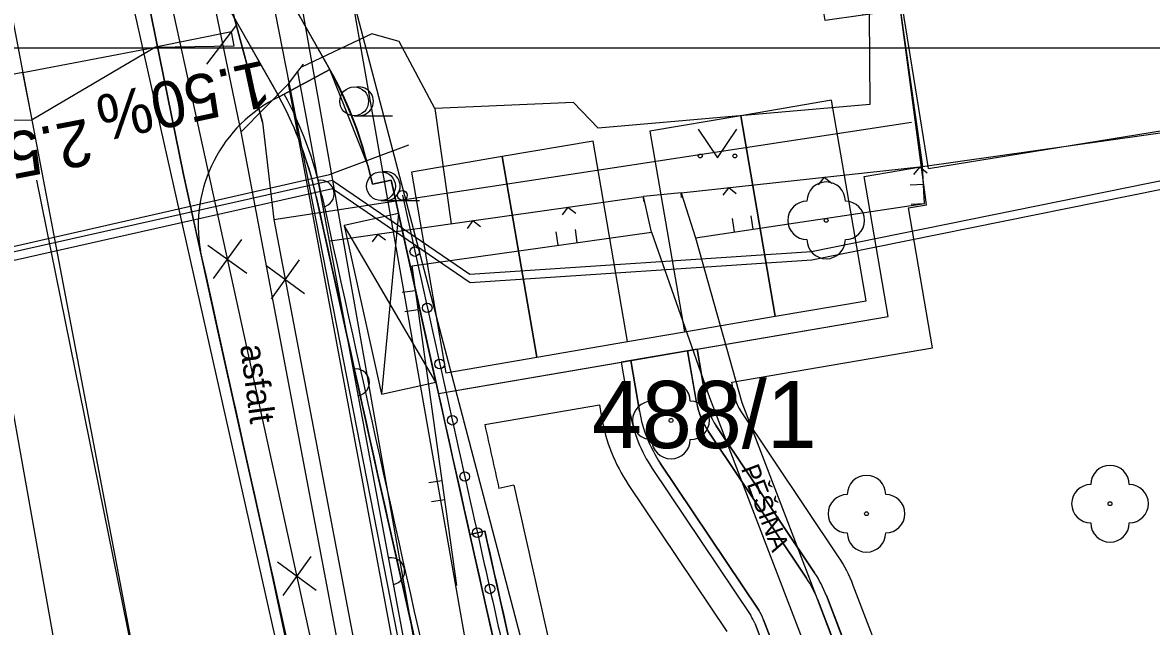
# Model space of a CAD drawing. Extents: x -643342 to -638635, y -1201752 to -1189948.
# Drawn here: x -639502.04 to -639472.65, y -1192680.44 to -1192664.71 of the extents above; entities that cross this region are included whole.
import ezdxf

# ---------------------------------------------------------------- set-up
doc = ezdxf.new("R2010")
doc.units = 0
for name, color, linetype in [('-zbytky_kruháče', 7, 'Continuous'), ('41', 7, 'Continuous'), ('5', 7, 'Continuous'), ('IS_EL_NN_NADZEMNÍ', 7, 'Continuous'), ('IS_TELEF_MISTNI_ZAMERENO', 7, 'Continuous'), ('IS_VODOVOD_PRIPOJKA DOMOVNÍ', 7, 'Continuous'), ('K-HRANICE_KN', 7, 'Continuous'), ('K-ČÍSLA_PARCEL', 7, 'Continuous'), ('kanalizace_dešťová_stávající', 7, 'Continuous'), ('N-CHODNIK', 7, 'Continuous'), ('N-CHODNIK-PŘÍMĚTICE', 7, 'Continuous'), ('N-KAN_DEST_TRASA-NÁVRH', 7, 'Continuous'), ('N-OBVOD STAVBY 06', 7, 'Continuous'), ('N-oploceni', 7, 'Continuous'), ('N-OSA', 7, 'Continuous'), ('N-PLOT', 7, 'Continuous'), ('N-rusene_vedeni', 7, 'Continuous'), ('N-SILNICE', 7, 'Continuous'), ('N-SO101_KLOPENI', 7, 'Continuous'), ('N-SRAFY_PLOCHY', 7, 'Continuous'), ('N-ZDI', 7, 'Continuous'), ('N-úprava plochu u obecního úřadu', 7, 'Continuous'), ('Vrstva 13', 7, 'Continuous'), ('Z-budovy', 7, 'Continuous'), ('Z-hrany_a_čáry', 7, 'Continuous'), ('Z-popisy', 7, 'Continuous'), ('Z-stromy', 7, 'Continuous'), ('Z-značky', 7, 'Continuous')]:
    doc.layers.add(name, color=color, linetype=linetype)

# ---------------------------------------------------------------- blocks, each defined once
blk = doc.blocks.new('RAMA24')
at = {"layer": 'Vrstva 13'}
for p in [(-29700, 0), (-21000, 0)]:
    blk.add_line(p, (0, 0), dxfattribs=at)

msp = doc.modelspace()

# ---------------------------------------------------------------- linework, layer by layer
at = {"layer": '-zbytky_kruháče'}
msp.add_line((-639501.68, -1192668.815), (-639498.7, -1192683.504), dxfattribs=at)
at = {"layer": '5'}
for p, q in [((-639478.686, -1192668.468), (-639478.843, -1192668.663)), ((-639478.686, -1192668.468), (-639478.491, -1192668.625)), ((-639478.586, -1192668.927), (-639478.935, -1192668.945)), ((-639478.56, -1192669.426), (-639478.909, -1192669.444))]:
    msp.add_line(p, q, dxfattribs=at)
at = {"layer": 'IS_EL_NN_NADZEMNÍ'}
for p, q in [((-639488.19, -1192693.98), (-639494.86, -1192656.13)), ((-639489.5, -1192694.06), (-639496.16, -1192656.39))]:
    msp.add_line(p, q, dxfattribs=at)
msp.add_lwpolyline([(-639495.51, -1192656.21), (-639485.819, -1192693.156)], dxfattribs=at)
at = {"layer": 'IS_TELEF_MISTNI_ZAMERENO'}
for p, q in [((-639498.66, -1192656.66), (-639495.8, -1192667.3)), ((-639495.8, -1192667.3), (-639498.66, -1192656.66)), ((-639495.8, -1192667.3), (-639495.5, -1192669.84)), ((-639495.5, -1192669.84), (-639478.9, -1192667.3)), ((-639495.5, -1192669.84), (-639490.34, -1192697.09))]:
    msp.add_line(p, q, dxfattribs=at)
at = {"layer": 'IS_VODOVOD_PRIPOJKA DOMOVNÍ'}
for points in [[(-639508.251, -1192671.127), (-639508.092, -1192671.093), (-639507.998, -1192671.075), (-639507.374, -1192671.693), (-639494.05, -1192668.667), (-639491.986, -1192667.889)], [(-639508.152, -1192671.995), (-639507.95, -1192671.95), (-639493.98, -1192668.81), (-639490.4, -1192671.26), (-639481.5, -1192670.67), (-639471.54, -1192668.65), (-639471.232, -1192668.584)], [(-639508.128, -1192672.212), (-639507.94, -1192672.17), (-639493.97, -1192669.03), (-639490.39, -1192671.48), (-639481.49, -1192670.89), (-639471.53, -1192668.87), (-639471.212, -1192668.802)]]:
    msp.add_lwpolyline(points, dxfattribs=at)
at = {"layer": 'K-HRANICE_KN'}
for p, q in [((-639490.92, -1192687.58), (-639497.61, -1192653.45)), ((-639478.46, -1192668.51), (-639479.13, -1192664.31)), ((-639478.46, -1192668.51), (-639470.96, -1192667.29))]:
    msp.add_line(p, q, dxfattribs=at)
at = {"layer": 'kanalizace_dešťová_stávající'}
msp.add_lwpolyline([(-639501.4, -1192649.45), (-639493.45, -1192685.76), (-639489, -1192707.04), (-639487.73, -1192718.33)], dxfattribs=at)
at = {"layer": 'N-CHODNIK'}
for p, q in [((-639492.252, -1192669.679), (-639492.695, -1192674.386)), ((-639491.279, -1192674.072), (-639493.668, -1192669.992))]:
    msp.add_line(p, q, dxfattribs=at)
msp.add_lwpolyline([(-639492.252, -1192669.679), (-639493.668, -1192669.992), (-639492.695, -1192674.386), (-639491.279, -1192674.072)], close=True, dxfattribs=at)
at = {"layer": 'N-CHODNIK-PŘÍMĚTICE'}
for p, q in [((-639494.154, -1192665.729), (-639497.026, -1192660.652)), ((-639495.46, -1192666.467), (-639498.331, -1192661.391)), ((-639495.363, -1192666.642), (-639494.043, -1192665.93)), ((-639492.932, -1192668.919), (-639492.444, -1192668.812))]:
    msp.add_line(p, q, dxfattribs=at)
for centre, radius, start, end in [((-639504.164, -1192671.391), 11.5, 12.4113, 29.4957), ((-639504.164, -1192671.391), 10, 12.4113, 29.4957), ((-639504.164, -1192671.391), 10.15, 12.4113, 28.3512), ((-636647.689, -1192042.763), 2912.828, 192.411302, 192.702157), ((-636647.689, -1192042.763), 2914.828, 192.411302, 192.702157), ((-636647.688, -1192042.763), 2914.679, 192.411302, 192.702157)]:
    msp.add_arc(centre, radius, start, end, dxfattribs=at)
at = {"layer": 'N-KAN_DEST_TRASA-NÁVRH'}
msp.add_lwpolyline([(-639583.962, -1192528.01), (-639550.452, -1192564.184), (-639529.583, -1192588.026), (-639514.491, -1192612.048), (-639507.737, -1192644.326), (-639498.832, -1192694.254), (-639511.439, -1192713.331), (-639516.613, -1192716.507), (-639553.938, -1192703.739), (-639570.485, -1192701.616), (-639578.687, -1192703.18)], dxfattribs=at)
at = {"layer": 'N-OBVOD STAVBY 06'}
for points in [[(-639483.574, -1192674.073), (-639478.35, -1192673.177), (-639478.975, -1192669.537), (-639478.509, -1192669.457), (-639479.189, -1192664.375), (-639480.16, -1192664.511), (-639480.679, -1192661.378), (-639479.62, -1192661.17), (-639480.18, -1192657.1), (-639473.476, -1192655.963), (-639474.659, -1192649.068), (-639480.958, -1192650.354), (-639492.683, -1192652.747), (-639494.955, -1192656.085)], [(-639483.514, -1192674.42), (-639483.574, -1192674.073)], [(-639490.011, -1192675.178), (-639487.024, -1192674.665)], [(-639487.024, -1192674.665), (-639486.967, -1192674.995)], [(-639480.798, -1192678.624), (-639483.363, -1192674.79)], [(-639489.25, -1192676.757), (-639489.64, -1192676.844)], [(-639486.272, -1192676.736), (-639483.707, -1192680.57)], [(-639474.551, -1192702.67), (-639474.362, -1192695.153), (-639480.414, -1192679.366)]]:
    msp.add_lwpolyline(points, dxfattribs=at)
for centre, radius, start, end in [((-639482.532, -1192674.234), 1, 190.7418, 213.7845), ((-636647.689, -1192042.763), 2911.828, 192.543933, 192.577514), ((-639482.532, -1192674.234), 4.5, 189.7364, 213.7845), ((-635637.009, -1191816.112), 3947.21, 192.593871, 192.685804), ((-639483.916, -1192680.709), 3.751, 20.9887, 33.7821)]:
    msp.add_arc(centre, radius, start, end, dxfattribs=at)
at = {"layer": 'N-oploceni'}
for centre in [(-639492.156, -1192669.207), (-639491.832, -1192670.672), (-639491.508, -1192672.137), (-639491.182, -1192673.601), (-639490.856, -1192675.065), (-639490.53, -1192676.53), (-639490.203, -1192677.994), (-639489.875, -1192679.457)]:
    msp.add_circle(centre, 0.125, dxfattribs=at)
for centre, radius, start, end in [((-636647.689, -1192042.763), 2912.628, 192.42012, 192.597178), ((-636648.374, -1192042.917), 2911.926, 192.597169, 192.702169)]:
    msp.add_arc(centre, radius, start, end, dxfattribs=at)
at = {"layer": 'N-OSA'}
msp.add_lwpolyline([(-639498.81, -1192682.926), (-639506.825, -1192640.839)], dxfattribs=at)
at = {"layer": 'N-PLOT'}
for points in [[(-639484.729, -1192673.257), (-639479.505, -1192672.361), (-639480.13, -1192668.721), (-639478.61, -1192668.46)], [(-639491.018, -1192674.336), (-639486.207, -1192673.511)]]:
    msp.add_lwpolyline(points, dxfattribs=at)
at = {"layer": 'N-rusene_vedeni'}
for p, q in [((-639496.345, -1192670.361), (-639497.077, -1192671.374)), ((-639497.217, -1192670.502), (-639496.204, -1192671.233)), ((-639495.712, -1192671.029), (-639494.699, -1192671.761)), ((-639494.84, -1192670.889), (-639495.571, -1192671.902)), ((-639494.538, -1192678.614), (-639495.27, -1192679.627)), ((-639495.41, -1192678.755), (-639494.397, -1192679.487))]:
    msp.add_line(p, q, dxfattribs=at)
at = {"layer": 'N-SILNICE'}
msp.add_line((-639497.852, -1192668.663), (-639500.522, -1192655.528), dxfattribs=at)
for centre, radius, start, end in [((-639493.725, -1192670.01), 3.745, 115.9414, 189.8695), ((-636647.693, -1192042.764), 2918.074, 192.385621, 192.66671)]:
    msp.add_arc(centre, radius, start, end, dxfattribs=at)
at = {"layer": 'N-SO101_KLOPENI'}
for points in [[(-639496.606, -1192664.951), (-639498.578, -1192665.348), (-639496.538, -1192665.316), (-639496.606, -1192664.951)], [(-639502.032, -1192666.011), (-639498.578, -1192665.348), (-639501.797, -1192667.239), (-639502.032, -1192666.011)], [(-639502.032, -1192666.011), (-639498.578, -1192665.348), (-639501.797, -1192667.239), (-639502.032, -1192666.011)], [(-639502.032, -1192666.011), (-639508.542, -1192667.256), (-639501.797, -1192667.239), (-639502.032, -1192666.011)]]:
    msp.add_lwpolyline(points, close=True, dxfattribs=at)
at = {"layer": 'N-SRAFY_PLOCHY'}
for p, q in [((-639500.535, -1192655.464), (-639497.852, -1192668.663)), ((-639494.043, -1192665.93), (-639497.026, -1192660.652)), ((-639495.363, -1192666.642), (-639498.331, -1192661.391)), ((-639498.331, -1192661.391), (-639495.363, -1192666.642)), ((-639496.428, -1192661.709), (-639494.666, -1192664.824)), ((-639498.437, -1192665.785), (-639498.993, -1192663.053)), ((-639478.61, -1192668.46), (-639479.189, -1192664.375)), ((-639494.666, -1192664.824), (-639494.043, -1192665.93)), ((-639497.852, -1192668.663), (-639498.437, -1192665.785)), ((-639494.043, -1192665.93), (-639495.363, -1192666.642)), ((-639495.363, -1192666.642), (-639494.043, -1192665.93)), ((-639493.053, -1192668.423), (-639492.932, -1192668.919)), ((-639497.463, -1192670.433), (-639497.852, -1192668.663)), ((-639497.852, -1192668.663), (-639497.415, -1192670.652)), ((-639480.13, -1192668.721), (-639478.61, -1192668.46)), ((-639492.932, -1192668.919), (-639492.444, -1192668.812)), ((-639492.444, -1192668.812), (-639492.932, -1192668.919)), ((-639492.444, -1192668.812), (-639491.212, -1192674.369)), ((-639490.398, -1192678.037), (-639492.444, -1192668.812)), ((-639479.505, -1192672.361), (-639480.13, -1192668.721)), ((-639494.397, -1192669.241), (-639493.598, -1192672.853)), ((-639492.798, -1192676.465), (-639494.397, -1192669.241)), ((-639496.938, -1192672.813), (-639497.463, -1192670.433)), ((-639497.415, -1192670.652), (-639496.308, -1192675.652)), ((-639485.098, -1192673.32), (-639479.505, -1192672.361)), ((-639496.409, -1192675.197), (-639496.938, -1192672.813)), ((-639493.598, -1192672.853), (-639492.798, -1192676.465)), ((-639484.729, -1192673.257), (-639486.207, -1192673.511)), ((-639485.838, -1192673.447), (-639485.098, -1192673.32)), ((-639484.482, -1192673.215), (-639484.729, -1192673.257)), ((-639484.499, -1192674.597), (-639484.729, -1192673.257)), ((-639484.729, -1192673.257), (-639484.503, -1192674.572)), ((-639484.257, -1192674.53), (-639484.482, -1192673.215)), ((-639491.212, -1192674.369), (-639485.838, -1192673.447)), ((-639486.207, -1192673.511), (-639486.454, -1192673.553)), ((-639486.454, -1192673.553), (-639486.228, -1192674.868)), ((-639486.207, -1192673.511), (-639485.981, -1192674.826)), ((-639485.981, -1192674.826), (-639486.207, -1192673.511)), ((-639496.093, -1192676.622), (-639496.409, -1192675.197)), ((-639481.629, -1192679.18), (-639484.194, -1192675.346)), ((-639484.194, -1192675.346), (-639481.629, -1192679.18)), ((-639481.422, -1192679.041), (-639483.986, -1192675.207)), ((-639496.308, -1192675.652), (-639494.747, -1192682.638)), ((-639485.649, -1192676.319), (-639483.084, -1192680.153)), ((-639485.441, -1192676.18), (-639482.876, -1192680.014)), ((-639482.876, -1192680.014), (-639485.441, -1192676.18)), ((-639495.633, -1192678.683), (-639496.093, -1192676.622)), ((-639492.798, -1192676.465), (-639491.989, -1192680.075)), ((-639491.18, -1192683.684), (-639492.798, -1192676.465)), ((-639490.008, -1192677.95), (-639490.398, -1192678.037)), ((-639489.229, -1192683.245), (-639490.398, -1192678.037)), ((-639490.398, -1192678.037), (-639489.229, -1192683.245)), ((-639488.839, -1192683.157), (-639490.008, -1192677.95)), ((-639494.881, -1192682.21), (-639495.633, -1192678.683)), ((-639474.439, -1192697.747), (-639481.348, -1192679.724)), ((-639481.348, -1192679.724), (-639474.439, -1192697.747)), ((-639474.431, -1192697.068), (-639481.114, -1192679.634)), ((-639491.989, -1192680.075), (-639491.18, -1192683.684)), ((-639482.981, -1192680.351), (-639476.32, -1192697.73)), ((-639482.748, -1192680.261), (-639476.086, -1192697.64)), ((-639476.086, -1192697.64), (-639482.748, -1192680.261))]:
    msp.add_line(p, q, dxfattribs=at)
for centre, radius, start, end in [((-639502.453, -1192670.712), 9.675, 13.6827, 29.6226), ((-639504.164, -1192671.391), 11.5, 12.4113, 28.3512), ((-639493.725, -1192670.01), 3.745, 115.9414, 189.8695), ((-639493.725, -1192670.01), 3.745, 115.9414, 189.8695), ((-639504.164, -1192671.391), 10, 12.4113, 28.3512), ((-639504.164, -1192671.391), 10, 12.4113, 28.3512), ((-639482.532, -1192674.234), 2, 189.7364, 213.7845), ((-639482.532, -1192674.234), 2, 190.4493, 213.7845), ((-639482.532, -1192674.234), 1.75, 189.7364, 213.7853), ((-639482.532, -1192674.234), 3.75, 189.7364, 213.7845), ((-639482.532, -1192674.234), 3.5, 189.7364, 213.7845), ((-639482.532, -1192674.234), 3.5, 189.7364, 213.7845), ((-639483.915, -1192680.709), 2.75, 20.9911, 33.7845), ((-639483.915, -1192680.709), 2.75, 20.9911, 33.7845), ((-639483.915, -1192680.709), 3, 20.9911, 33.7845), ((-639483.915, -1192680.709), 1, 20.9911, 33.7845), ((-639483.915, -1192680.709), 1.25, 21.0132, 33.7845), ((-639483.915, -1192680.709), 1.25, 20.9911, 33.7845)]:
    msp.add_arc(centre, radius, start, end, dxfattribs=at)
at = {"layer": 'N-ZDI'}
msp.add_line((-639490.398, -1192678.037), (-639490.008, -1192677.95), dxfattribs=at)
msp.add_arc((-636647.689, -1192042.763), 2912.428, 192.597182, 192.702157, dxfattribs=at)
at = {"layer": 'N-úprava plochu u obecního úřadu'}
for p, q in [((-639493.053, -1192668.423), (-639494.043, -1192665.93)), ((-639486.292, -1192673.018), (-639484.813, -1192672.764)), ((-639485.838, -1192673.447), (-639485.098, -1192673.32)), ((-639484.729, -1192673.257), (-639484.503, -1192674.572)), ((-639484.482, -1192673.215), (-639484.257, -1192674.53)), ((-639486.454, -1192673.553), (-639486.228, -1192674.868)), ((-639486.207, -1192673.511), (-639485.981, -1192674.826)), ((-639484.194, -1192675.346), (-639481.629, -1192679.18)), ((-639483.986, -1192675.207), (-639481.422, -1192679.041)), ((-639485.649, -1192676.319), (-639483.084, -1192680.153)), ((-639485.441, -1192676.18), (-639482.876, -1192680.014))]:
    msp.add_line(p, q, dxfattribs=at)
for points in [[(-639493.053, -1192668.423), (-639492.932, -1192668.919), (-639492.444, -1192668.812), (-639491.212, -1192674.369), (-639485.838, -1192673.447), (-639485.098, -1192673.32), (-639479.505, -1192672.361), (-639480.13, -1192668.721), (-639478.61, -1192668.46), (-639479.189, -1192664.375), (-639481.15, -1192664.65), (-639481.66, -1192661.57), (-639479.62, -1192661.17), (-639480.18, -1192657.1), (-639474.463, -1192656.123), (-639475.639, -1192649.269), (-639480.958, -1192650.354), (-639491.279, -1192652.46), (-639494.129, -1192656.648)], [(-639497.026, -1192660.652), (-639496.428, -1192661.709), (-639494.666, -1192664.824), (-639494.043, -1192665.93)], [(-639480.979, -1192666.729), (-639483.344, -1192667.135), (-639482.448, -1192672.358), (-639480.082, -1192671.952), (-639480.979, -1192666.729)], [(-639483.344, -1192667.135), (-639485.71, -1192667.54), (-639484.813, -1192672.764), (-639482.448, -1192672.358), (-639483.344, -1192667.135)], [(-639487.188, -1192667.794), (-639489.553, -1192668.2), (-639488.657, -1192673.424), (-639486.292, -1192673.018), (-639487.188, -1192667.794)], [(-639489.553, -1192668.2), (-639491.919, -1192668.606), (-639491.023, -1192673.83), (-639488.657, -1192673.424), (-639489.553, -1192668.2)], [(-639481.348, -1192679.724), (-639474.439, -1192697.747), (-639474.553, -1192702.67)], [(-639481.114, -1192679.634), (-639474.431, -1192697.068)], [(-639482.982, -1192680.35), (-639476.32, -1192697.73)], [(-639482.748, -1192680.261), (-639476.086, -1192697.64)]]:
    msp.add_lwpolyline(points, dxfattribs=at)
for centre, radius, start, end in [((-639502.453, -1192670.712), 9.675, 13.6827, 29.6226), ((-639482.532, -1192674.234), 2, 189.7364, 213.7845), ((-639482.532, -1192674.234), 1.75, 189.7364, 213.7853), ((-639482.532, -1192674.234), 3.75, 189.7364, 213.7845), ((-639482.532, -1192674.234), 3.5, 189.7364, 213.7845), ((-639483.915, -1192680.709), 2.75, 20.9911, 33.7845), ((-639483.915, -1192680.709), 3, 20.9911, 33.7845), ((-639483.915, -1192680.709), 1, 20.9911, 33.7845), ((-639483.915, -1192680.709), 1.25, 20.9911, 33.7845)]:
    msp.add_arc(centre, radius, start, end, dxfattribs=at)
at = {"layer": 'Z-budovy'}
msp.add_lwpolyline([(-639472.53, -1192655.81), (-639476.42, -1192656.44), (-639480.18, -1192657.1), (-639479.62, -1192661.17), (-639479.46, -1192662.36), (-639479.35, -1192663.24), (-639478.61, -1192668.46), (-639470.892, -1192667.366), (-639472.53, -1192655.81)], dxfattribs=at)
at = {"layer": 'Z-hrany_a_čáry'}
for p, q in [((-639496.35, -1192667.55), (-639497.55, -1192661.8)), ((-639499.62, -1192662.27), (-639494.29, -1192685.96)), ((-639497.249, -1192665.793), (-639496.465, -1192664.766)), ((-639495.12, -1192666.3), (-639494.875, -1192665.979)), ((-639494.875, -1192665.979), (-639494.73, -1192665.79)), ((-639491.275, -1192685.264), (-639494.875, -1192665.979)), ((-639496.35, -1192667.55), (-639495.12, -1192666.3)), ((-639491.57, -1192685.32), (-639495.12, -1192666.3)), ((-639491.31, -1192666.95), (-639490.886, -1192669.947)), ((-639492.94, -1192685.57), (-639496.35, -1192667.55)), ((-639484.9, -1192669.14), (-639478.61, -1192668.46)), ((-639483.657, -1192669.006), (-639483.814, -1192669.201)), ((-639483.657, -1192669.006), (-639483.462, -1192669.163)), ((-639481.172, -1192668.737), (-639481.329, -1192668.932)), ((-639481.172, -1192668.737), (-639480.977, -1192668.894)), ((-639494.031, -1192670.392), (-639485.88, -1192669.24)), ((-639484.9, -1192669.14), (-639485.88, -1192669.24)), ((-639485.867, -1192669.364), (-639485.88, -1192669.24)), ((-639484.887, -1192669.264), (-639484.9, -1192669.14)), ((-639487.843, -1192669.517), (-639487.993, -1192669.717)), ((-639487.843, -1192669.517), (-639487.642, -1192669.668)), ((-639490.318, -1192669.867), (-639490.468, -1192670.067)), ((-639490.318, -1192669.867), (-639490.118, -1192670.018)), ((-639483.511, -1192670.159), (-639483.563, -1192669.813)), ((-639483.017, -1192670.086), (-639483.069, -1192669.739)), ((-639488.097, -1192670.509), (-639488.146, -1192670.162)), ((-639487.602, -1192670.44), (-639487.65, -1192670.093)), ((-639485.67, -1192670.17), (-639484.16, -1192674.47)), ((-639492.793, -1192670.217), (-639492.944, -1192670.417)), ((-639492.793, -1192670.217), (-639492.593, -1192670.368)), ((-639484.52, -1192670.31), (-639483.32, -1192674.6)), ((-639491.809, -1192671.694), (-639492.156, -1192671.742)), ((-639491.74, -1192672.189), (-639492.087, -1192672.238)), ((-639484.16, -1192674.47), (-639475.245, -1192697.704)), ((-639483.32, -1192674.6), (-639474.439, -1192697.747)), ((-639491.119, -1192676.646), (-639491.466, -1192676.695)), ((-639491.05, -1192677.142), (-639491.397, -1192677.19))]:
    msp.add_line(p, q, dxfattribs=at)
for points in [[(-639480, -1192664.49), (-639479.98, -1192666.84), (-639487.06, -1192667.46), (-639487.7, -1192666.79), (-639491.31, -1192666.95), (-639492.24, -1192665.2), (-639492.95, -1192665), (-639494.78, -1192665.87)], [(-639484.9, -1192669.14), (-639484.52, -1192670.31), (-639478.56, -1192669.42), (-639478.61, -1192668.46)], [(-639490.74, -1192679.37), (-639491.9, -1192671.04), (-639485.67, -1192670.17), (-639485.88, -1192669.24)]]:
    msp.add_lwpolyline(points, dxfattribs=at)
for centre in [(-639494.28, -1192669.165), (-639493.363, -1192674.08), (-639492.445, -1192678.996)]:
    msp.add_arc(centre, 0.35, 280.5739, 100.5739, dxfattribs=at)
at = {"layer": 'Z-stromy'}
for centre in [(-639481.12, -1192669.86), (-639485.16, -1192675.07), (-639473.73, -1192677.24), (-639480.07, -1192677.5)]:
    msp.add_circle(centre, 0.05, dxfattribs=at)
for centre, start, end in [((-639481.12, -1192669.36), 0, 180), ((-639481.62, -1192669.86), 90, 270), ((-639480.62, -1192669.86), 270, 90), ((-639481.12, -1192670.36), 180, 0), ((-639485.16, -1192674.57), 0, 180), ((-639485.66, -1192675.07), 90, 270), ((-639484.66, -1192675.07), 270, 90), ((-639485.16, -1192675.57), 180, 0), ((-639473.73, -1192676.74), 0, 180), ((-639480.07, -1192677), 0, 180), ((-639474.23, -1192677.24), 90, 270), ((-639473.23, -1192677.24), 270, 90), ((-639480.57, -1192677.5), 90, 270), ((-639479.57, -1192677.5), 270, 90), ((-639473.73, -1192677.74), 180, 0), ((-639480.07, -1192678), 180, 0)]:
    msp.add_arc(centre, 0.5, start, end, dxfattribs=at)
at = {"layer": 'Z-značky'}
for p, q in [((-639493.41, -1192667.133), (-639492.41, -1192667.133)), ((-639492.712, -1192669.343), (-639491.712, -1192669.343))]:
    msp.add_line(p, q, dxfattribs=at)
msp.add_lwpolyline([(-639484.449, -1192667.481), (-639483.949, -1192668.231), (-639483.449, -1192667.481)], dxfattribs=at)
for centre, radius in [((-639493.41, -1192666.758), 0.375), ((-639484.399, -1192668.181), 0.05), ((-639483.5, -1192668.181), 0.05), ((-639492.712, -1192668.968), 0.375)]:
    msp.add_circle(centre, radius, dxfattribs=at)
for centre in [(-639493.285, -1192666.758), (-639492.587, -1192668.968)]:
    msp.add_arc(centre, 0.375, 260.4059, 99.5941, dxfattribs=at)

# ---------------------------------------------------------------- block references
at = {"layer": '41', "xscale": 0.01, "yscale": 0.01}
msp.add_blockref('RAMA24', (-639343.591, -1192665.365), dxfattribs=at)

# ---------------------------------------------------------------- texts
at = {"layer": 'K-ČÍSLA_PARCEL'}
msp.add_text('488/1', height=1.75, dxfattribs=at).set_placement((-639487.221, -1192675.791))
at = {"layer": 'N-SO101_KLOPENI'}
for s, rotation, p in [('1.50%', 192.0823, (-639495.754, -1192665.685)), ('2.50%', 190.8409, (-639500.366, -1192667.201))]:
    msp.add_text(s, height=1.2, rotation=rotation, dxfattribs=at).set_placement(p)
at = {"layer": 'Z-popisy'}
for s, height, rotation, p in [('asfalt', 0.65, 277.4213, (-639496.38, -1192673.119)), ('PĚŠINA', 0.48, 290.5167, (-639483.344, -1192676.324))]:
    msp.add_text(s, height=height, rotation=rotation, dxfattribs=at).set_placement(p)

doc.saveas('drawing.dxf')
